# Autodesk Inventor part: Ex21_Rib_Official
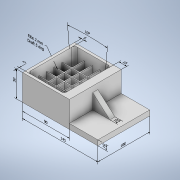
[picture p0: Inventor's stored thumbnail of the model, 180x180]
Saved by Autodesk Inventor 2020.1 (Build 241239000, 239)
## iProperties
Created: 2019-11
Part Number: Ex21_Rib_Official
Material: Generic
Document SubType Name: Modeling
Designer: Synergysoft Dell02
Density: 1 g/cm^3
Appearance: Default
Author: Synergysoft Dell02
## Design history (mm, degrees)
node "Annotations"
  node "Linear Dimension 1" dims "d40" = 145 (derived)
  node "Linear Dimension 2" dims "d41" = 90 (derived)
  node "Linear Dimension 3" dims "d42" = 100 (derived)
  node "Linear Dimension 4" dims "d45" = 50 (derived)
  node "Linear Dimension 5" dims "d46" = 10 (derived)
  node "Angular Dimension 1" dims "d49" = 10 deg (derived)
  node "Linear Dimension 6" dims "d52" = 5 (derived)
  node "Linear Dimension 7" dims "d55" = 15 (derived)
  node "Linear Dimension 8" dims "d58" = 5 (derived)
  node "Linear Dimension 11" dims "d65" = 10 (derived)
  node "Leader Text 1"
sketch "Sketch1"
  geometry: L1 (0, 0)-(-80, 0); L2 (-80, 0)-(-80, 50); L3 (-80, 50)-(0, 50); L4 (0, 50)-(0, 0); L5 (0, 50)-(10, 50); L6 (10, 50)-(10, 10); L7 (10, 10)-(65, 10); L8 (65, 10)-(65, 0); L9 (65, 0)-(0, 0)
  constraints: 18 end point, 5 perpendicular, 2 horizontal, 2 parallel
  dimensions: "d0" = 80 distance of L2.end L3.end; "d1" = 50 distance of L1.end L2.end; "d2" = 10 distance of L3.end L5.end; "d3" = 40 distance of L5.end L6.end; "d4" = 65 distance of L8.end L1.start
extrude "Extrusion1" new body sketch "Sketch1" distance "d5" = 100; taper "d6" = 0 deg
sketch "Sketch2"
  geometry: L1 (80, 0)-(0, 0) reference; L2 (0, 0)-(0, -100) reference; L3 (80, -100)-(0, -100) reference; L4 (80, 0)-(80, -100) reference; L5 (5, -5)-(75, -5); L6 (75, -5)-(75, -95); L7 (75, -95)-(5, -95); L8 (5, -95)-(5, -5); 1 further point
  constraints: 8 end point, 3 other
  dimensions: "d7" = 5 distance between parallel lines of L1 L5
extrude "Extrusion2" cut sketch "Sketch2" distance "d8" = 35; taper "d9" = -5 deg
fillet "Fillet1" dims "d10" = 5
fillet "Fillet2" dims "d11" = 5
extrude "Extrusion3" join sketch "Sketch1" stored distance "d12" = 10; taper "d13" = 0 deg
workplane "Work Plane1"
sketch "Sketch3"
  geometry: L1 (-80, 0)-(-80, 50) reference; L2 (-80, 50)-(-75, 50) reference; L3 (-75, 50)-(-72.337, 19.564) reference; L4 (-67.356, 15)-(-12.644, 15) reference; L5 (-7.663, 19.564)-(-5, 50) reference; L6 (-5, 50)-(10, 50) reference; L7 (10, 50)-(10, 10) reference; L8 (10, 10)-(65, 10) reference; L9 (65, 10)-(65, 0) reference; L10 (65, 0)-(-80, 0) reference; L11 (-67.356, 15)-(-12.644, 15) reference; L12 (-35, 15)-(-5.962, 39); L13 (10, 10)-(10, 50) reference; L14 (10, 39)-(43, 10); L15 (65, 10)-(10, 10) reference; A1 r 5 centre (-67.356, 20) between (-72.337, 19.564) and (-67.356, 15) reference; A2 r 5 centre (-12.644, 20) between (-12.644, 15) and (-7.663, 19.564) reference; 1 further point
  constraints: 4 end point, 4 point on line
feature "Rib1" sketch "Sketch3" dims "d14" = 5, "d15" = 10, "d16" = 0, "d17" = 0, "d18" = 1, "d19" = 1
workplane "Work Plane2"
sketch "Sketch4"
  geometry: L1 (-90, 0)-(-90, -100) reference; L2 (-90, -100)-(55, -100) reference; L3 (-65, -22)-(-65, -72); L4 (-50, -22)-(-50, -72); L5 (-35, -22)-(-35, -72); L6 (-73.949, -75)-(-23.949, -75); L7 (-73.949, -60)-(-23.949, -60); L8 (-73.949, -45)-(-23.949, -45); L9 (-73.949, -30)-(-23.949, -30); 1 further point
  constraints: 14 end point, 5 parallel, 1 horizontal, 1 vertical
  dimensions: "d21" = 50 distance of L3.start L3.end; "d22" = 25 distance between parallel lines of L3 L1; "d23" = 15 distance between parallel lines of L3 L4; "d24" = 15 distance between parallel lines of L4 L5; "d25" = 50 distance of L6.start L6.end; "d26" = 25 distance between parallel lines of L6 L2; "d27" = 15 distance between parallel lines of L6 L7; "d28" = 15 distance between parallel lines of L7 L8; "d29" = 15 distance between parallel lines of L8 L9
feature "Rib2" sketch "Sketch4" dims "d30" = 2, "d31" = 5, "d32" = 5 deg, "d33" = 0, "d34" = 1, "d35" = 1
fillet "Fillet3" dims "d36" = 0.5
fillet "Fillet4" dims "d37" = 0.5
body "Solid1"
node "Projected Loop1"
node "Project Cut Edges1"
other parameters: "d20" = 25, "d47" = 9.36339 (derived), "d48" = 3.47124 (derived), "d50" = 8.34261 (derived), "d51" = 2.41135 (derived), "d53" = 2.7792 (derived), "d54" = 2.6034 (derived), "d56" = 8.75252 (derived), "d57" = 0.70702 (derived), "d66" = 3.96071 (derived), "d67" = 3.96071 (derived)
